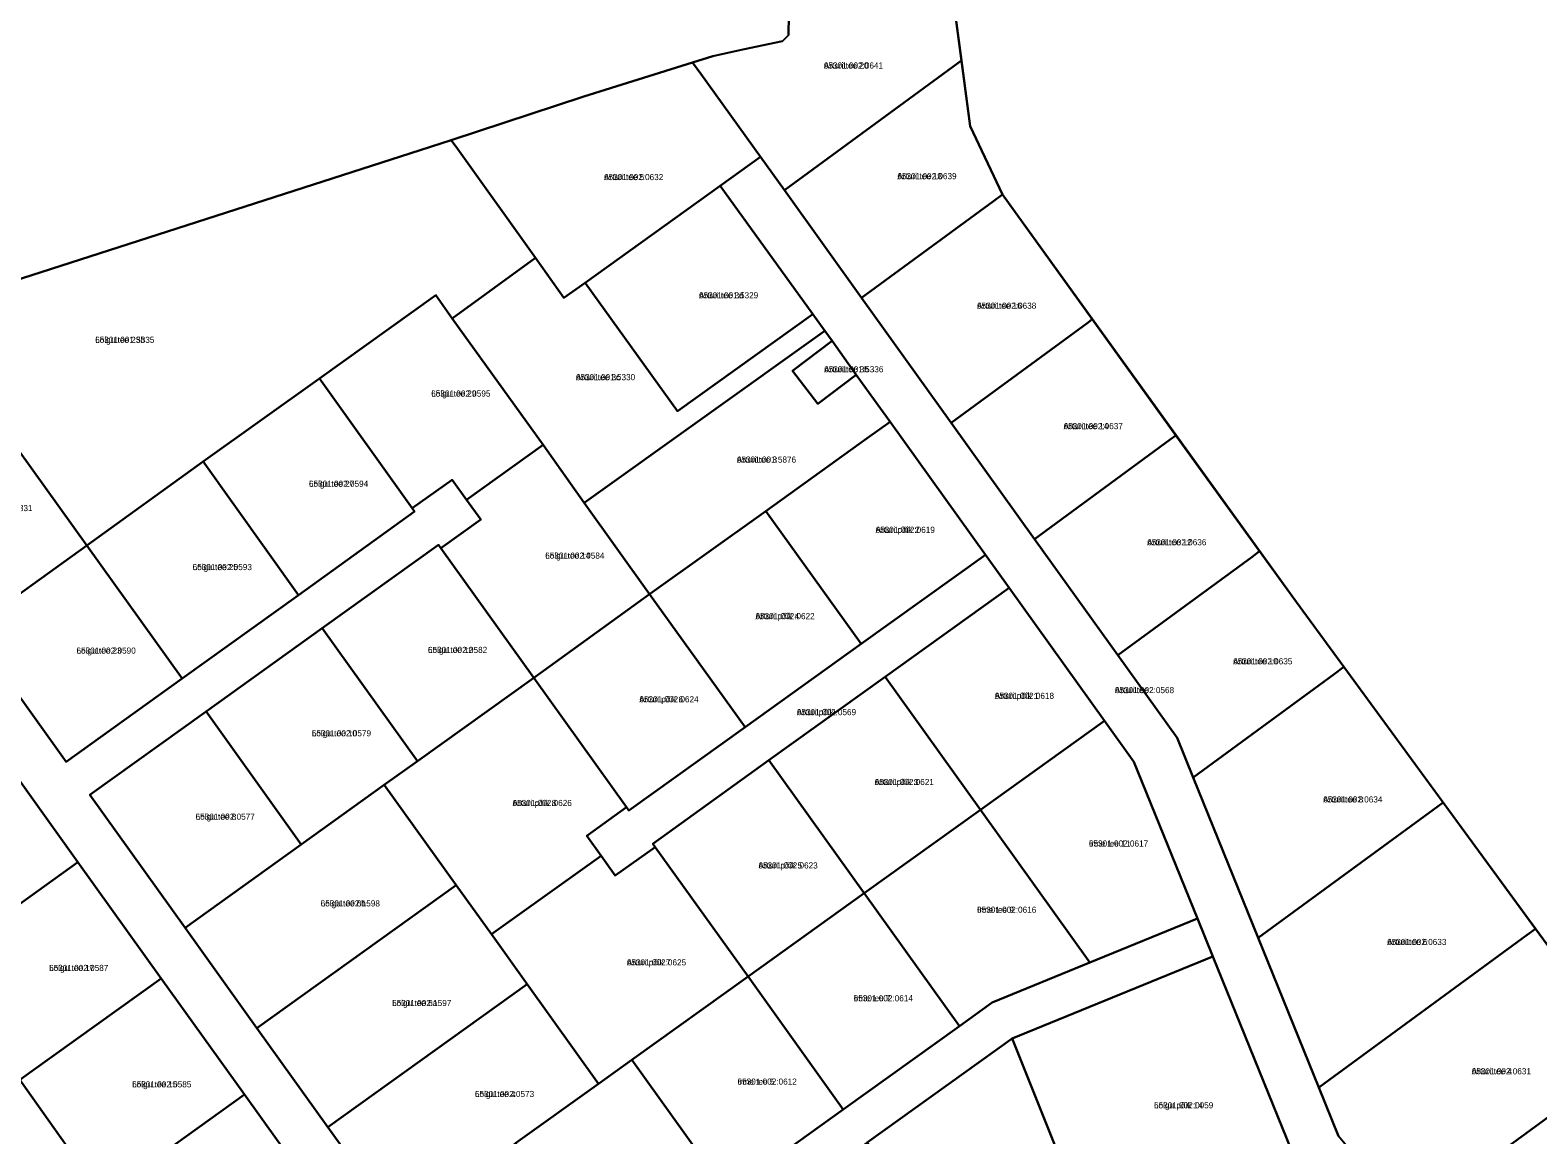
# Model space of a CAD drawing. Extents: x 543236 to 563717, y 6566033 to 6588992.
# Drawn here: x 547510.5 to 547879.6, y 6584476.1 to 6584746.4 of the extents above; entities that cross this region are included whole.
import ezdxf

# ---------------------------------------------------------------- set-up
doc = ezdxf.new("R2010")
doc.units = 0
for name, color, linetype in [('L_AADRESS', 7, 'Continuous'), ('PIIR', 7, 'Continuous'), ('TUNNUS', 7, 'Continuous')]:
    doc.layers.add(name, color=color, linetype=linetype)

msp = doc.modelspace()

# ---------------------------------------------------------------- linework, layer by layer
at = {"layer": 'PIIR'}
for points in [[(547954.94, 6584897.14), (548418, 6584661.07), (548073.21, 6584219.71), (547822.9, 6584045.85), (547791.34, 6584089.91), (547762.23, 6584130.56), (547726.58, 6584180.33), (547703.79, 6584212.15), (547681.42, 6584243.38), (547673.85, 6584253.95), (547904.47, 6584445.32), (547908.07, 6584486.9), (547820.46, 6584606.43), (547748.48, 6584706.18), (547740.64, 6584722.91), (547735.69, 6584759.78), (547742.32, 6584763.93)], [(547696.44, 6584766.82), (547706.73, 6584765.06), (547735.69, 6584759.78), (547738.48, 6584739), (547735.15, 6584736.56), (547695.15, 6584707.25), (547689.3, 6584715.41), (547674.7, 6584735.75), (547672.67, 6584738.55), (547677.58, 6584740.09), (547684.98, 6584741.66), (547694.64, 6584743.71), (547696.11, 6584745.19), (547696.19, 6584750.12), (547696.37, 6584762.08)], [(547738.48, 6584739), (547740.64, 6584722.91), (547748.48, 6584706.18), (547746.3, 6584704.58), (547714.03, 6584680.93), (547695.15, 6584707.25), (547735.15, 6584736.56)], [(547615.18, 6584717.34), (547613.59, 6584719.54), (547646.06, 6584730.2), (547672.67, 6584738.55), (547674.7, 6584735.75), (547689.3, 6584715.41), (547679.44, 6584708.38), (547646.39, 6584684.63), (547641.16, 6584680.92), (547634.18, 6584690.75)], [(547613.59, 6584719.54), (547615.18, 6584717.34), (547634.18, 6584690.75), (547613.83, 6584675.85), (547609.77, 6584681.55), (547581.32, 6584661.16), (547552.89, 6584640.86), (547524.38, 6584620.31), (547497.44, 6584657.74), (547468.8, 6584637.71), (547461.95, 6584633.06), (547398.5, 6584652.97), (547390.52, 6584655.58), (547400.33, 6584654.78), (547401.26, 6584655.01), (547403.91, 6584655.67), (547407.32, 6584655.42), (547410.98, 6584654.97), (547415.29, 6584655.42), (547421.34, 6584657.72), (547426.43, 6584659.37), (547498.9, 6584682.65), (547605.95, 6584717.04)], [(547668.95, 6584653.24), (547646.39, 6584684.63), (547679.44, 6584708.38), (547702.08, 6584676.97)], [(547748.48, 6584706.18), (547770.49, 6584675.68), (547769.49, 6584674.94), (547735.96, 6584650.36), (547714.03, 6584680.93), (547746.3, 6584704.58)], [(547641.16, 6584680.92), (547646.39, 6584684.63), (547668.95, 6584653.24), (547702.08, 6584676.97), (547705.06, 6584672.83), (547646.15, 6584630.81), (547636.04, 6584644.96), (547613.83, 6584675.85), (547634.18, 6584690.75)], [(547609.77, 6584681.55), (547613.83, 6584675.85), (547636.04, 6584644.96), (547617.28, 6584631.55), (547613.78, 6584636.43), (547604.03, 6584629.44), (547581.32, 6584661.16)], [(547662.13, 6584608.4), (547646.15, 6584630.81), (547705.06, 6584672.83), (547706.79, 6584670.41), (547697.14, 6584663.11), (547703.28, 6584655.01), (547712.72, 6584662.09), (547716.93, 6584656.24), (547721.02, 6584650.59), (547715.36, 6584646.57), (547690.58, 6584628.74)], [(547770.49, 6584675.68), (547790.97, 6584647.29), (547789.57, 6584646.26), (547756.36, 6584621.92), (547735.96, 6584650.36), (547769.49, 6584674.94)], [(547697.14, 6584663.11), (547706.79, 6584670.41), (547712.72, 6584662.09), (547703.28, 6584655.01)], [(547475.45, 6584628.55), (547468.8, 6584637.71), (547497.44, 6584657.74), (547524.38, 6584620.31), (547495.97, 6584599.91), (547488.87, 6584609.84)], [(547581.32, 6584661.16), (547604.03, 6584629.44), (547604.61, 6584628.62), (547576.17, 6584608.22), (547552.89, 6584640.86)], [(547721.02, 6584650.59), (547744.34, 6584618.09), (547713.95, 6584596.29), (547690.58, 6584628.74), (547715.36, 6584646.57)], [(547790.97, 6584647.29), (547811.45, 6584618.91), (547809.56, 6584617.52), (547776.76, 6584593.48), (547756.36, 6584621.92), (547789.57, 6584646.26)], [(547636.04, 6584644.96), (547646.15, 6584630.81), (547662.13, 6584608.4), (547633.76, 6584587.99), (547611.03, 6584619.68), (547620.78, 6584626.68), (547617.28, 6584631.55)], [(547552.89, 6584640.86), (547576.17, 6584608.22), (547547.73, 6584587.82), (547524.38, 6584620.31)], [(547690.58, 6584628.74), (547713.95, 6584596.29), (547685.51, 6584575.89), (547662.13, 6584608.4)], [(547524.38, 6584620.31), (547547.73, 6584587.82), (547519.29, 6584567.42), (547495.97, 6584599.91)], [(547610.44, 6584620.5), (547611.03, 6584619.68), (547633.76, 6584587.99), (547605.32, 6584567.59), (547582, 6584600.1)], [(547744.34, 6584618.09), (547750.17, 6584609.96), (547719.78, 6584588.17), (547691.34, 6584567.77), (547662.9, 6584547.37), (547663.48, 6584546.55), (547653.73, 6584539.56), (547650.24, 6584544.43), (547646.74, 6584549.31), (547656.49, 6584556.3), (547657.07, 6584555.49), (547685.51, 6584575.89), (547713.95, 6584596.29)], [(547811.45, 6584618.91), (547820.46, 6584606.43), (547832.05, 6584590.61), (547829.69, 6584588.88), (547795.18, 6584563.59), (547791.25, 6584573.28), (547776.76, 6584593.48), (547809.56, 6584617.52)], [(547750.17, 6584609.96), (547773.48, 6584577.46), (547743.1, 6584555.66), (547719.78, 6584588.17)], [(547662.13, 6584608.4), (547685.51, 6584575.89), (547657.07, 6584555.49), (547656.49, 6584556.3), (547633.76, 6584587.99)], [(547582, 6584600.1), (547605.32, 6584567.59), (547597.19, 6584561.77), (547576.88, 6584547.19), (547553.56, 6584579.7)], [(547633.76, 6584587.99), (547656.49, 6584556.3), (547646.74, 6584549.31), (547650.24, 6584544.43), (547623.42, 6584525.2), (547614.79, 6584537.24), (547597.19, 6584561.77), (547605.32, 6584567.59)], [(547719.78, 6584588.17), (547743.1, 6584555.66), (547714.66, 6584535.26), (547691.34, 6584567.77)], [(547832.05, 6584590.61), (547856.35, 6584557.46), (547853.91, 6584555.67), (547811.11, 6584524.3), (547795.18, 6584563.59), (547829.69, 6584588.88)], [(547553.56, 6584579.7), (547576.88, 6584547.19), (547548.44, 6584526.79), (547525.12, 6584559.3)], [(547773.48, 6584577.46), (547780.67, 6584567.44), (547796.24, 6584529.04), (547769.91, 6584518.28), (547743.1, 6584555.66)], [(547498.83, 6584575.36), (547522.15, 6584542.86), (547490, 6584519.8), (547487.67, 6584518.13), (547464.22, 6584551.11), (547466.5, 6584552.71)], [(547691.34, 6584567.77), (547714.66, 6584535.26), (547686.22, 6584514.86), (547663.48, 6584546.55), (547662.9, 6584547.37)], [(547597.19, 6584561.77), (547614.79, 6584537.24), (547566.03, 6584502.26), (547548.44, 6584526.79), (547576.88, 6584547.19)], [(547743.1, 6584555.66), (547769.91, 6584518.28), (547745.99, 6584508.51), (547737.97, 6584502.76), (547714.66, 6584535.26)], [(547856.35, 6584557.46), (547878.99, 6584526.57), (547876.96, 6584525.09), (547825.95, 6584487.7), (547811.11, 6584524.3), (547853.91, 6584555.67)], [(547650.24, 6584544.43), (547653.73, 6584539.56), (547663.48, 6584546.55), (547686.22, 6584514.86), (547657.78, 6584494.46), (547649.65, 6584488.63), (547632.16, 6584513.01), (547623.42, 6584525.2)], [(547522.15, 6584542.86), (547542.55, 6584514.42), (547510.92, 6584491.73), (547507.95, 6584489.6), (547487.67, 6584518.13), (547490, 6584519.8)], [(547614.79, 6584537.24), (547623.42, 6584525.2), (547632.16, 6584513.01), (547583.41, 6584478.04), (547566.03, 6584502.26)], [(547714.66, 6584535.26), (547737.97, 6584502.76), (547709.53, 6584482.36), (547686.22, 6584514.86)], [(547796.24, 6584529.04), (547800, 6584519.77), (547750.86, 6584499.7), (547715.36, 6584474.23), (547686.92, 6584453.83), (547658.48, 6584433.43), (547630.04, 6584413.03), (547624.21, 6584421.16), (547652.65, 6584441.56), (547681.09, 6584461.96), (547709.53, 6584482.36), (547737.97, 6584502.76), (547745.99, 6584508.51), (547769.91, 6584518.28)], [(547878.99, 6584526.57), (547902.04, 6584495.12), (547900.01, 6584493.63), (547847.76, 6584455.33), (547830.78, 6584475.79), (547825.95, 6584487.7), (547876.96, 6584525.09)], [(547820.36, 6584469.56), (547772.89, 6584444.67), (547750.86, 6584499.7), (547800, 6584519.77)], [(547542.55, 6584514.42), (547562.95, 6584485.98), (547531.95, 6584463.74), (547528.23, 6584461.08), (547507.95, 6584489.6), (547510.92, 6584491.73)], [(547686.22, 6584514.86), (547709.53, 6584482.36), (547681.09, 6584461.96), (547657.78, 6584494.46)], [(547632.16, 6584513.01), (547649.65, 6584488.63), (547629.34, 6584474.06), (547606.58, 6584457.74), (547602.5, 6584463.43), (547596.82, 6584459.35), (547583.41, 6584478.04)], [(547750.86, 6584499.7), (547765.71, 6584462.62), (547747.69, 6584449.71), (547737.96, 6584442.73), (547715.36, 6584474.23)], [(547657.78, 6584494.46), (547681.09, 6584461.96), (547652.65, 6584441.56), (547629.34, 6584474.06), (547649.65, 6584488.63)], [(547902.04, 6584495.12), (547908.07, 6584486.9), (547905.08, 6584452.32), (547872.61, 6584425.38), (547847.76, 6584455.33), (547900.01, 6584493.63)], [(547562.95, 6584485.98), (547583.35, 6584457.54), (547551.49, 6584434.69), (547548.58, 6584432.6), (547543.32, 6584439.85), (547528.23, 6584461.08), (547531.95, 6584463.74)]]:
    msp.add_lwpolyline(points, close=True, dxfattribs=at)
for points in [[(547410.44, 6584816.76), (547524.17, 6584796.92), (547619.67, 6584780.25), (547696.44, 6584766.82), (547696.37, 6584762.08), (547696.19, 6584750.12), (547696.11, 6584745.19), (547694.64, 6584743.71), (547684.98, 6584741.66), (547677.58, 6584740.09), (547672.67, 6584738.55), (547646.06, 6584730.2), (547613.59, 6584719.54), (547605.95, 6584717.04), (547498.9, 6584682.65)], [(547820.36, 6584469.56), (547800, 6584519.77), (547796.24, 6584529.04), (547780.67, 6584567.44), (547773.48, 6584577.46), (547750.17, 6584609.96), (547744.34, 6584618.09), (547721.02, 6584650.59), (547716.93, 6584656.24), (547712.72, 6584662.09), (547706.79, 6584670.41), (547705.06, 6584672.83), (547702.08, 6584676.97), (547679.44, 6584708.38), (547689.3, 6584715.41), (547695.15, 6584707.25), (547714.03, 6584680.93), (547735.96, 6584650.36), (547756.36, 6584621.92), (547776.76, 6584593.48), (547791.25, 6584573.28), (547795.18, 6584563.59), (547811.11, 6584524.3), (547825.95, 6584487.7), (547830.78, 6584475.79)], [(547214.58, 6584431.86), (547258.17, 6584485.37), (547313.31, 6584553.23), (547362.18, 6584612.06), (547381.94, 6584637.66), (547389.25, 6584646.78), (547402.56, 6584639.68), (547426.83, 6584603.49), (547445.02, 6584578.4), (547464.22, 6584551.11), (547487.67, 6584518.13), (547507.95, 6584489.6), (547528.23, 6584461.08), (547543.32, 6584439.85), (547541.71, 6584438.59), (547515.08, 6584400.26), (547507.82, 6584389.8), (547481.19, 6584351.47), (547459.79, 6584320.66), (547431.46, 6584279.88)], [(547495.97, 6584599.91), (547519.29, 6584567.42), (547547.73, 6584587.82), (547576.17, 6584608.22), (547604.61, 6584628.62), (547604.03, 6584629.44), (547613.78, 6584636.43), (547617.28, 6584631.55), (547620.78, 6584626.68), (547611.03, 6584619.68), (547610.44, 6584620.5), (547582, 6584600.1), (547553.56, 6584579.7), (547525.12, 6584559.3), (547548.44, 6584526.79), (547566.03, 6584502.26), (547583.41, 6584478.04), (547596.82, 6584459.35)], [(547583.35, 6584457.54), (547562.95, 6584485.98), (547542.55, 6584514.42), (547522.15, 6584542.86), (547498.83, 6584575.36)]]:
    msp.add_lwpolyline(points, dxfattribs=at)

# ---------------------------------------------------------------- texts
at = {"layer": 'L_AADRESS'}
for s, p in [('Arturi tee 20', (547704.78, 6584737.04)), ('Arturi tee 5', (547650.98, 6584709.74)), ('Arturi tee 18', (547722.78, 6584709.96)), ('Arturi tee 3d', (547674.22, 6584680.81)), ('Arturi tee 16', (547742.28, 6584678.27)), ('Loigu tee 23b', (547526.42, 6584669.92)), ('Arturi tee 3c', (547644.1, 6584660.78)), ('Arturi tee 3b', (547704.86, 6584662.71)), ('Loigu tee 29', (547608.68, 6584656.77)), ('Arturi tee 14', (547763.48, 6584648.8)), ('Arturi tee 3', (547683.49, 6584640.61)), ('Loigu tee 27', (547578.75, 6584634.7)), ('Arturi põik 2', (547717.46, 6584623.43)), ('Arturi tee 12', (547783.92, 6584620.38)), ('Loigu tee 14', (547636.58, 6584617.11)), ('Loigu tee 25', (547550.28, 6584614.31)), ('Arturi põik 4', (547688.04, 6584602.31)), ('Loigu tee 23', (547521.85, 6584593.87)), ('Loigu tee 12', (547607.88, 6584594.04)), ('Arturi tee 10', (547804.97, 6584591.25)), ('Arturi põik 1', (547746.63, 6584582.81)), ('Arturi tee', (547776.02, 6584584.21)), ('Arturi põik 6', (547659.63, 6584581.97)), ('Arturi põik', (547698.18, 6584578.82)), ('Loigu tee 10', (547579.44, 6584573.65)), ('Arturi põik 3', (547717.22, 6584561.72)), ('Arturi põik 8', (547628.59, 6584556.59)), ('Arturi tee 8', (547827.01, 6584557.46)), ('Loigu tee 8', (547551, 6584553.24)), ('Irme tee 11', (547769.67, 6584546.67)), ('Arturi põik 5', (547688.78, 6584541.31)), ('Loigu tee 6b', (547581.62, 6584532.02)), ('Irme tee 9', (547742.28, 6584530.46)), ('Arturi tee 6', (547842.67, 6584522.58)), ('Loigu tee 17', (547515.14, 6584516.23)), ('Arturi põik 7', (547656.57, 6584517.59)), ('Irme tee 7', (547712.09, 6584508.81)), ('Loigu tee 6a', (547599.1, 6584507.64)), ('Arturi tee 4', (547863.37, 6584490.95)), ('Loigu tee 15', (547535.47, 6584487.75)), ('Irme tee 5', (547683.66, 6584488.41)), ('Loigu tee 4', (547619.37, 6584485.38)), ('Loigu põik 14', (547785.61, 6584482.62))]:
    msp.add_text(s, height=1.5, dxfattribs=at).set_placement(p)
at = {"layer": 'TUNNUS'}
for s, p in [('65301:002:0641', (547704.78, 6584737.04)), ('65301:002:0632', (547650.98, 6584709.74)), ('65301:002:0639', (547722.78, 6584709.96)), ('65301:001:5329', (547674.22, 6584680.81)), ('65301:002:0638', (547742.28, 6584678.27)), ('65301:001:5335', (547526.42, 6584669.92)), ('65301:001:5330', (547644.1, 6584660.78)), ('65301:001:5336', (547704.86, 6584662.71)), ('65301:002:0595', (547608.68, 6584656.77)), ('65301:002:0637', (547763.48, 6584648.8)), ('65301:001:5876', (547683.49, 6584640.61)), ('65301:002:0594', (547578.75, 6584634.7)), ('65301:001:5331', (547496.59, 6584628.75)), ('65301:002:0619', (547717.46, 6584623.43)), ('65301:002:0636', (547783.92, 6584620.38)), ('65301:002:0584', (547636.58, 6584617.11)), ('65301:002:0593', (547550.28, 6584614.31)), ('65301:002:0622', (547688.04, 6584602.31)), ('65301:002:0590', (547521.85, 6584593.87)), ('65301:002:0582', (547607.88, 6584594.04)), ('65301:002:0635', (547804.97, 6584591.25)), ('65301:002:0618', (547746.63, 6584582.81)), ('65301:002:0568', (547776.02, 6584584.21)), ('65301:002:0624', (547659.63, 6584581.97)), ('65301:002:0569', (547698.18, 6584578.82)), ('65301:002:0579', (547579.44, 6584573.65)), ('65301:002:0621', (547717.22, 6584561.72)), ('65301:002:0626', (547628.59, 6584556.59)), ('65301:002:0634', (547827.01, 6584557.46)), ('65301:002:0577', (547551, 6584553.24)), ('65301:002:0617', (547769.67, 6584546.67)), ('65301:002:0623', (547688.78, 6584541.31)), ('65301:002:1598', (547581.62, 6584532.02)), ('65301:002:0616', (547742.28, 6584530.46)), ('65301:002:0633', (547842.67, 6584522.58)), ('65301:002:0587', (547515.14, 6584516.23)), ('65301:002:0625', (547656.57, 6584517.59)), ('65301:002:0614', (547712.09, 6584508.81)), ('65301:002:1597', (547599.1, 6584507.64)), ('65301:002:0631', (547863.37, 6584490.95)), ('65301:002:0585', (547535.47, 6584487.75)), ('65301:002:0612', (547683.66, 6584488.41)), ('65301:002:0573', (547619.37, 6584485.38)), ('65301:002:0059', (547785.61, 6584482.62))]:
    msp.add_text(s, height=1.5, dxfattribs=at).set_placement(p)

doc.saveas('drawing.dxf')
